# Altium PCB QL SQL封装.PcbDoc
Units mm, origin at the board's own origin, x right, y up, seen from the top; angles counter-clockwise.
Board outline 59.99 x 32 mm, 2 copper layers (Top Layer, Bottom Layer); 0 components, 14 nets, 9 pads, 0 vias.
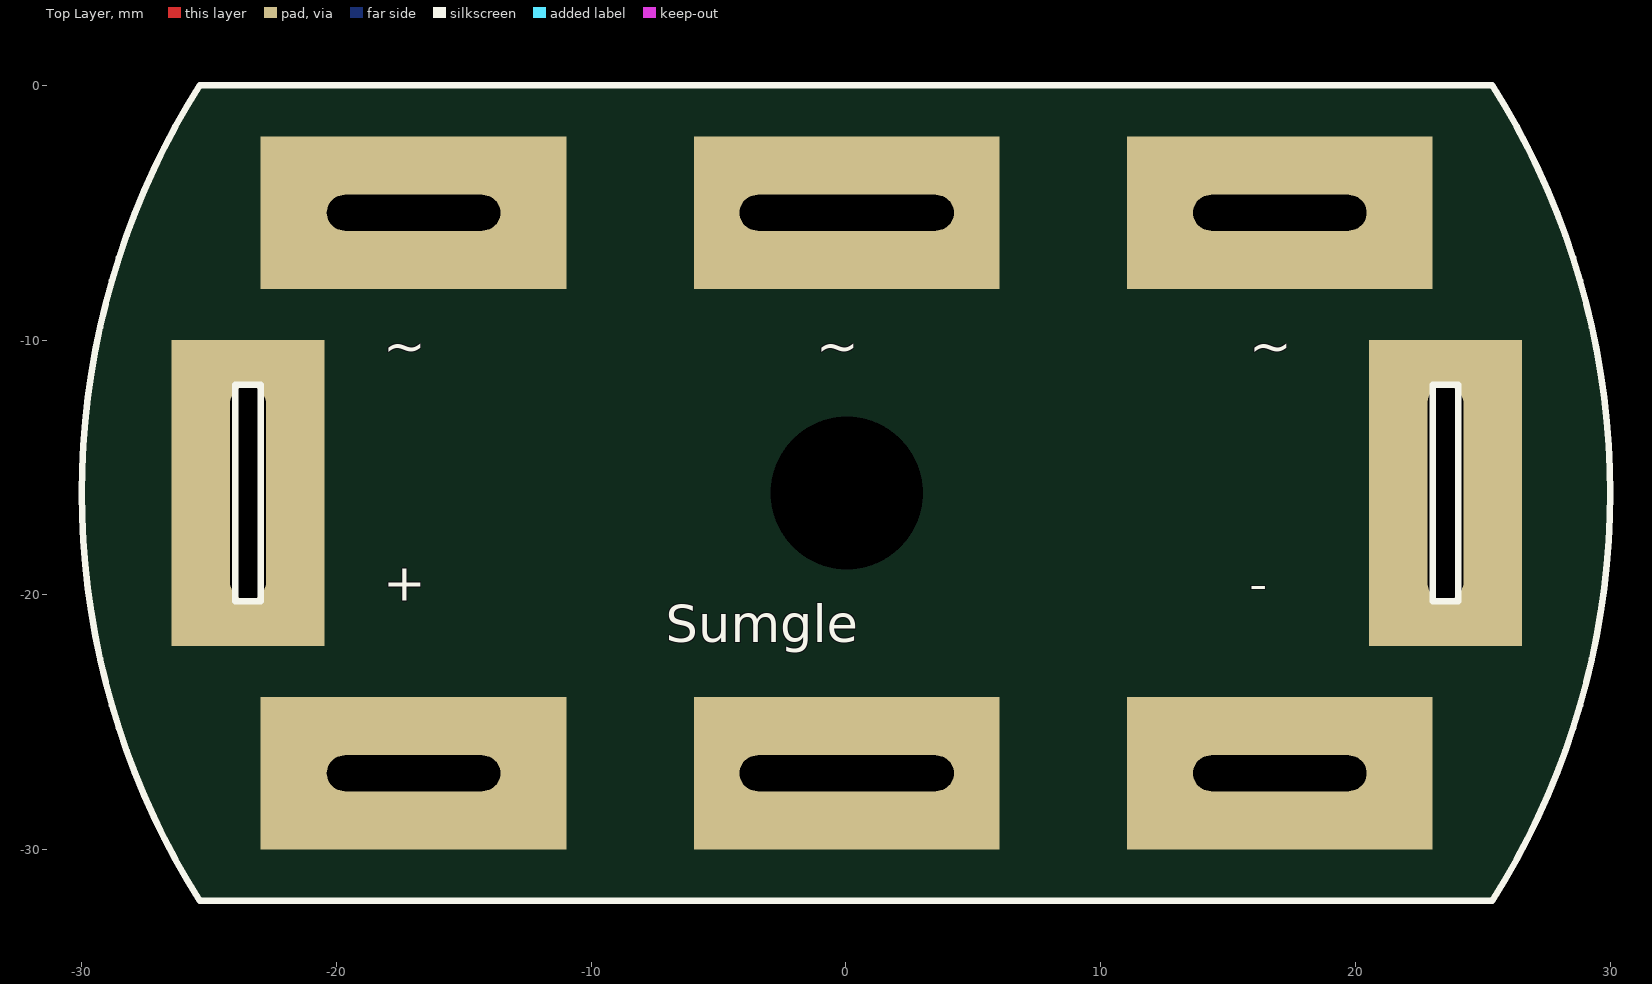
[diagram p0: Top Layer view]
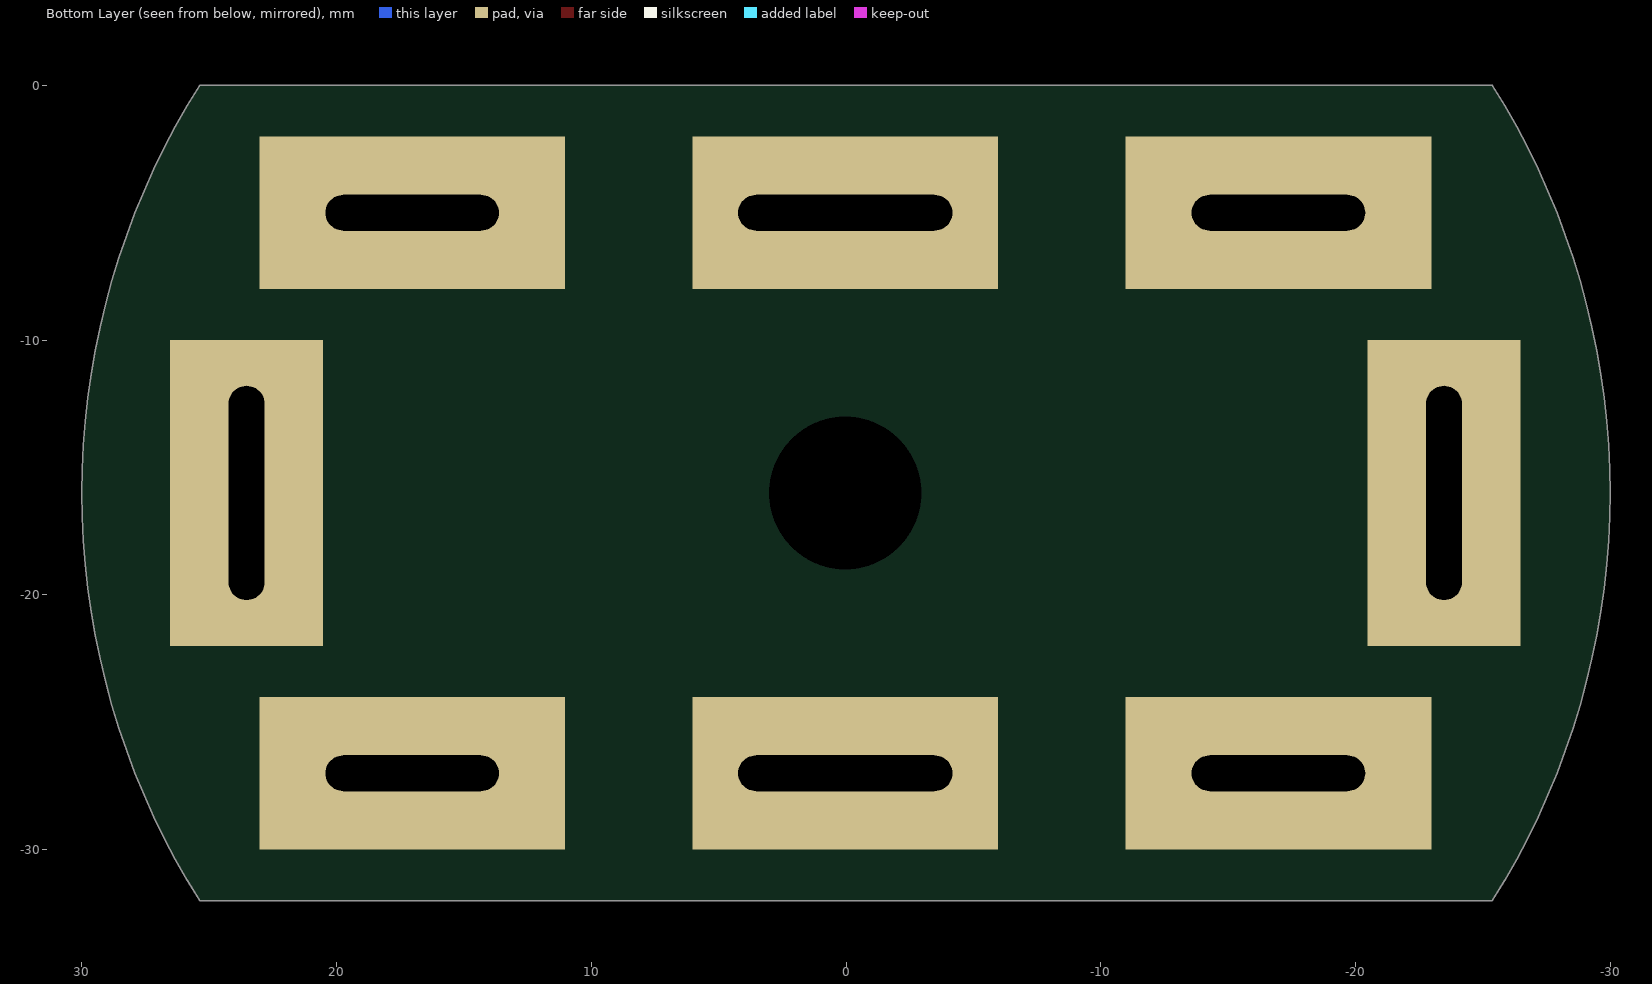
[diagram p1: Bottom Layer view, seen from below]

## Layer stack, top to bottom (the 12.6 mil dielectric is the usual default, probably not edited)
Top Layer: signal copper 0.0356
Dielectric: dielectric 0.32, FR-4, Dk 4.8
Bottom Layer: signal copper 0.0356

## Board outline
-25.372,-32.002 cw(c0.028,-16) -25.372,0.002 -25.372,0 25.372,0 25.372,0.002 cw(c-0.027,-16) 25.372,-32.002 25.372,-32

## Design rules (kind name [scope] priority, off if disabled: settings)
Clearance [All] p1: gap=0.254
PolygonConnect [All] p1: connectstyle=Relief reliefconductorwidth=0.254 reliefentries=4 polygonreliefangle="90 Angle"
RoutingVias [All] p1: holewidth=0.711 width=1.27 viastyle="Through Hole" minholewidth=0.711 minwidth=1.27 maxholewidth=0.711 maxwidth=1.27
SilkscreenOverComponentPads [All] p1: minsilkscreentomaskgap=0.254
SolderMaskExpansion [All] p1: expansion=0.102
Width [All] p1: maxlimit=3 minlimit=0.254 preferedwidth=0.254 minimp=50.000000 maximp=50.000000 favimp=50.000000
27 further rules are at their usual default settings.

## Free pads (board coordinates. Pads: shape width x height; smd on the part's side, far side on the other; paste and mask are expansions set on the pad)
  round 0 hole 6: 0(0.028,-16)
  rect 6x12 hole 1.4 slot 8.4 at 90 deg: 1(-23.473,-16) 2(23.528,-16)
  rect 12x6 hole 1.4 slot 6.8 at 0 deg: 1(-16.972,-27) 2(17.028,-27) 4(17.028,-5) 6(-16.972,-5)
  rect 12x6 hole 1.4 slot 8.4 at 0 deg: 4(0.028,-27) 6(0.028,-5)

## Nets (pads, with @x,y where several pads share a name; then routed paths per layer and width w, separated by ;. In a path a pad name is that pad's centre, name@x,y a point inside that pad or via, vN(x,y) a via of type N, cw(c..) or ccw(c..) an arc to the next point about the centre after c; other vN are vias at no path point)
GND: 
NetC3_2: 
NetC5_1: 
NetCFF_2: 
NetD1_2: 
NetL1_1: 
NetL2_2: 
NetMC2_10: 
V: 
VAUX: 
VAUX2: 
VCELL: 
VOUT: 
VOUT2: 

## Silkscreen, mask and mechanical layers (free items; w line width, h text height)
Top Overlay:
  lines w0.254: -25.372,-32.002 cw(c0.028,-16) -25.372,0.002 ; -25.372,-32 25.372,-32 ; -25.372,0 25.372,0 ; 25.372,-32.002 ccw(c-0.027,-16) 25.372,0.002 ; -23.972,-20.25 -23.972,-11.75 -22.973,-11.75 -22.973,-20.25 -23.972,-20.25 ; 23.028,-20.25 23.028,-11.75 24.027,-11.75 24.027,-20.25 23.028,-20.25
  text "~" at -18.171,-11.419 h2.5
  text "~" at -1.171,-11.419 h2.5
  text "~" at 15.829,-11.419 h2.5
  text "+" at -18.171,-20.725 h2.5
  text "-" at 15.829,-20.718 h2.5
  text "Sumgle" at -7.084,-22.35 h2.5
